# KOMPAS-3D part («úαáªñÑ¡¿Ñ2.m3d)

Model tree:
1. Ломаная:1
2. Эскиз:1
3. Кинематическая операция:1
     Толщина стенки 1 = 1; Толщина стенки 2 = 0.3
4. Смещенная плоскость:1
     Расстояние = 5.2
5. Зеркальный массив:1  (with: Кинематическая операция:1)  (labels: Экземпляр ( 1 ); Экземпляр ( 2 ))
6. Эскиз:2
7. Операция выдавливания:1
     Расстояние 1 = 5.2; Расстояние 2 = 5.2
8. Смещенная плоскость:2
     Расстояние = 14
9. Эскиз:3
10. Операция выдавливания:2
     Расстояние 1 = 0.4; Расстояние 2 = 0.4
11. Ломаная:3
12. Эскиз:4
13. Кинематическая операция:2
     Толщина стенки 1 = 1; Толщина стенки 2 = 0.3
14. Эскиз:7
15. Операция выдавливания:4
     Расстояние 1 = 1.3; Расстояние 2 = 1.1
16. Эскиз:8
17. Вырезать элемент выдавливания:2
     Расстояние 2 = 4; Расстояние 1 = 4
18. Скругление:3
     Радиус = 0.1

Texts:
  ограждение  фары левое
  stalker61
  Сплав АЛ8  ГОСТ 1583-93
  Экземпляр ( 1 )
  Экземпляр ( 2 )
